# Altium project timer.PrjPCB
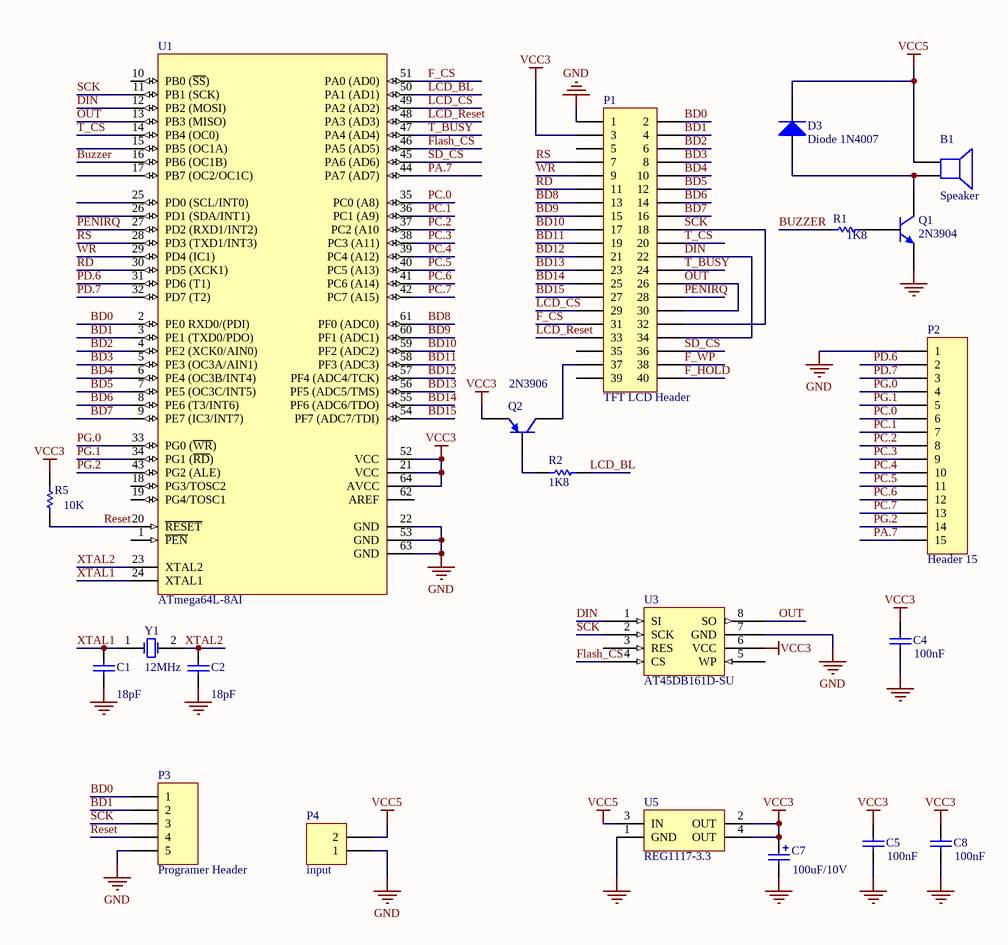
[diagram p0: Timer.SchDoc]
1 sheet, 21 parts. Net scope: global (net labels, ports and power ports of the same name join across sheets).
Board file: timer.PcbDoc

## Sheet Timer.SchDoc
size A4; PageSetup: Record=PageOptions|CenterHorizontal=True|CenterVertical=True|PrintScale=0.97|XCorrection=1.00|YCorrection=1.00|PrintKind=0|BorderSize=5000000|LeftOffset=0|BottomOffset=0|Orientation=2|PaperLength=1000|PaperWidth=1000|Scale=100|PaperSource=7|PrintQuality=-4|MediaType=1|DitherType=10|PaperKind=A4|PrintScaleMode=1

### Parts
B1  Speaker  [BUZZER]
C1  value 18pF  [RAD-0.1]  (hidden comment: Cap)
C2  value 18pF  [RAD-0.1]  (hidden comment: Cap)
C4  value 100nF  [RAD-0.1]  (hidden comment: Cap)
C5  value 100nF  [RAD-0.1]  (hidden comment: Cap)
C7  value 100uF/10V  [C100U]  (hidden comment: Cap Pol1)
C8  value 100nF  [RAD-0.1]  (hidden comment: Cap)
D3  Diode 1N4007  [DO-35]
P1  TFT LCD Header  [HDR2X20]
P2  Header 15  [HDR1X15]
P3  Programer Header  [HDR1X5]
P4  input  [HDR1X2]
Q1  2N3904  [TO92B]
Q2  2N3906  [TO92B]
R1  value 1K8  [Res0.125W]  (hidden comment: Res1)
R2  value 1K8  [Res0.125W]  (hidden comment: Res1)
R5  value 10K  [Res0.125W]  (hidden comment: Res1)
U1  ATmega64L-8AI  [ATMEL TQFP64]
U3  AT45DB161D-SU  [8S2_N]
U5  REG1117-3.3  [ZZ311]
Y1  value 12MHz  [XTAL]

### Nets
GND: C1.1 C2.1 C4.1 C5.1 C7.2 C8.1 P1.1 P2.1 P3.5 P4.1 Q1.1(E) U1.22(GND) U1.53(GND) U1.63(GND) U3.7(GND) U5.1(GND)
VCC3: C4.2 C5.2 C7.1 C8.2 P1.3 Q2.1(E) R5.2 U1.21(VCC) U1.52(VCC) U1.64(AVCC) U3.6(VCC) U5.2(OUT) U5.4(OUT)
VCC5: B1.1 D3.2(K) P4.2 U5.3(IN)
BD0: P1.2 P3.1 U1.2(PE0_RXD0/(PDI))
BD1: P1.4 P3.2 U1.3(PE1_(TXD0/PDO))
BD2: P1.6 U1.4(PE2_(XCK0/AIN0))
BD3: P1.8 U1.5(PE3_(OC3A/AIN1))
BD4: P1.10 U1.6(PE4_(OC3B/INT4))
BD5: P1.12 U1.7(PE5_(OC3C/INT5))
BD6: P1.14 U1.8(PE6_(T3/INT6))
BD7: P1.16 U1.9(PE7_(IC3/INT7))
BD8: P1.13 U1.61(PF0_(ADC0))
BD9: P1.15 U1.60(PF1_(ADC1))
BD10: P1.17 U1.59(PF2_(ADC2))
BD11: P1.19 U1.58(PF3_(ADC3))
BD12: P1.21 U1.57(PF4_(ADC4/TCK))
BD13: P1.23 U1.56(PF5_(ADC5/TMS))
BD14: P1.25 U1.55(PF6_(ADC6/TDO))
BD15: P1.27 U1.54(PF7_(ADC7/TDI))
BUZZER: R1.1 U1.16(PB6_(OC1B))
DIN: P1.22 P1.34 U1.12(PB2_(MOSI)) U3.1(SI)
F_CS: P1.31 U1.51(PA0_(AD0))
F_HOLD: P1.40
F_WP: P1.38
Flash_CS: U1.46(PA5_(AD5)) U3.4(CS)
LCD_BL: R2.2 U1.50(PA1_(AD1))
LCD_CS: P1.29 U1.49(PA2_(AD2))
LCD_Reset: P1.33 U1.48(PA3_(AD3))
OUT: P1.26 P1.30 U1.13(PB3_(MISO)) U3.8(SO)
PA.7: P2.15 U1.44(PA7_(AD7))
PC.0: P2.6 U1.35(PC0_(A8))
PC.1: P2.7 U1.36(PC1_(A9))
PC.2: P2.8 U1.37(PC2_(A10)
PC.3: P2.9 U1.38(PC3_(A11))
PC.4: P2.10 U1.39(PC4_(A12))
PC.5: P2.11 U1.40(PC5_(A13))
PC.6: P2.12 U1.41(PC6_(A14))
PC.7: P2.13 U1.42(PC7_(A15))
PD.6: P2.2 U1.31(PD6_(T1))
PD.7: P2.3 U1.32(PD7_(T2))
PENIRQ: P1.28 U1.27(PD2_(RXD1/INT2))
PG.0: P2.4 U1.33(PG0_(~{WR}))
PG.1: P2.5 U1.34(PG1_(~{RD}))
PG.2: P2.14 U1.43(PG2_(ALE))
RD: P1.11 U1.30(PD5_(XCK1))
Reset: P3.4 R5.1 U1.20(~{RESET})
RS: P1.7 U1.28(PD3_(TXD1/INT3))
SCK: P1.18 P1.32 P3.3 U1.11(PB1_(SCK)) U3.2(SCK)
SD_CS: P1.36 U1.45(PA6_(AD6))
T_BUSY: P1.24 U1.47(PA4_(AD4))
T_CS: P1.20 U1.14(PB4_(OC0))
WR: P1.9 U1.29(PD4_(IC1))
XTAL1: C1.2 U1.24(XTAL1) Y1.1(OSC1)
XTAL2: C2.2 U1.23(XTAL2) Y1.2(OSC2)
NetB1_2: B1.2 D3.1(A) Q1.3(C)
NetP1_37: P1.37 Q2.3(C)
NetQ1_2: Q1.2(B) R1.2
NetQ2_2: Q2.2(B) R2.1

Not connected (* = marked no-connect by the designer): P1 5 35 39; U1 1(~{PEN}) 10(PB0_(~{SS})) 15(PB5_(OC1A)) 17(PB7_(OC2/OC1C)) 18(PG3/TOSC2) 19(PG4/TOSC1) 25(PD0_(SCL/INT0)) 26(PD1_(SDA/INT1)) 62(AREF); U3 3(RES) 5(WP)

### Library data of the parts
B1 = Speaker: Loudspeaker
C1 C2 C4 C5 C8 = Cap: Capacitor
C7 = Cap Pol1: Polarized Capacitor (Radial)
D3 = Diode 1N4007: 1 Amp General Purpose Rectifier
P1 = Header 20X2: Header, 20-Pin, Dual row
P2 = Header 15: Header, 15-Pin
P3 = Header 5: Header, 5-Pin
P4 = Header 2: Header, 2-Pin
Q1 = 2N3904: NPN General Purpose Amplifier
Q2 = 2N3906: PNP General Purpose Amplifier
R1 R2 R5 = Res1: Resistor
U1 = ATmega64L-8AI: 8-Bit AVR Microcontroller with 64K Bytes of In-System Programmable Flash Memory
U5 = REG1117-3.3: 800mA and 1A Low Dropout Positive Regulator 2.85V, 3.3V, 5V, and Adjustable
Y1 = XTAL: Crystal Oscillator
